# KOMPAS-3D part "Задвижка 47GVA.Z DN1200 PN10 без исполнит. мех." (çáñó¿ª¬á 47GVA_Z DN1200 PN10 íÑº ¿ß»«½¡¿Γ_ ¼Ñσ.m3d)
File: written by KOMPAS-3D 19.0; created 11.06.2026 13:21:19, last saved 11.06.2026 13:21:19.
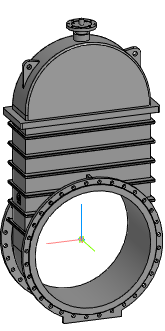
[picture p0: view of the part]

Document properties: Автор: Евгений; Полное имя файла: Z:\3.Личные\kachalov\001_3d для проектировщиков\2.2 Тип 47GVA, 47GVA.Z\_stp\_stp_Задвижка 47GVA.Z DN350-DN1200 без исп.мех\Задвижка 47GVA_Z DN1200 PN10 без исполнит_ мех.m3d

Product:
- Part/product: Задвижка 47GVA.Z DN1200 PN10 без исполнит. мех.

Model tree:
1. Операция без истории:1  (labels: Задвижка 47GVA.Z DN1200 PN10 без исполнит. мех.)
